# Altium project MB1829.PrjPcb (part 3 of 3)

## Sheet USBHS_TYPEC.SchDoc: USB HS Type-C
size A4; Date: Not used; ApprovedBy: Not used; CheckedBy: Not used; Author: Not used; CompanyName: STMicroelectronics; DrawnBy: Not used; Engineer: Not used; Organization: Not used; Address1: Not used; Address2: Not used; Address3: Not used; Address4: Not used; DocumentNumber: Not used; Revision: Not used; SheetNumber: 9; SheetTotal: 16
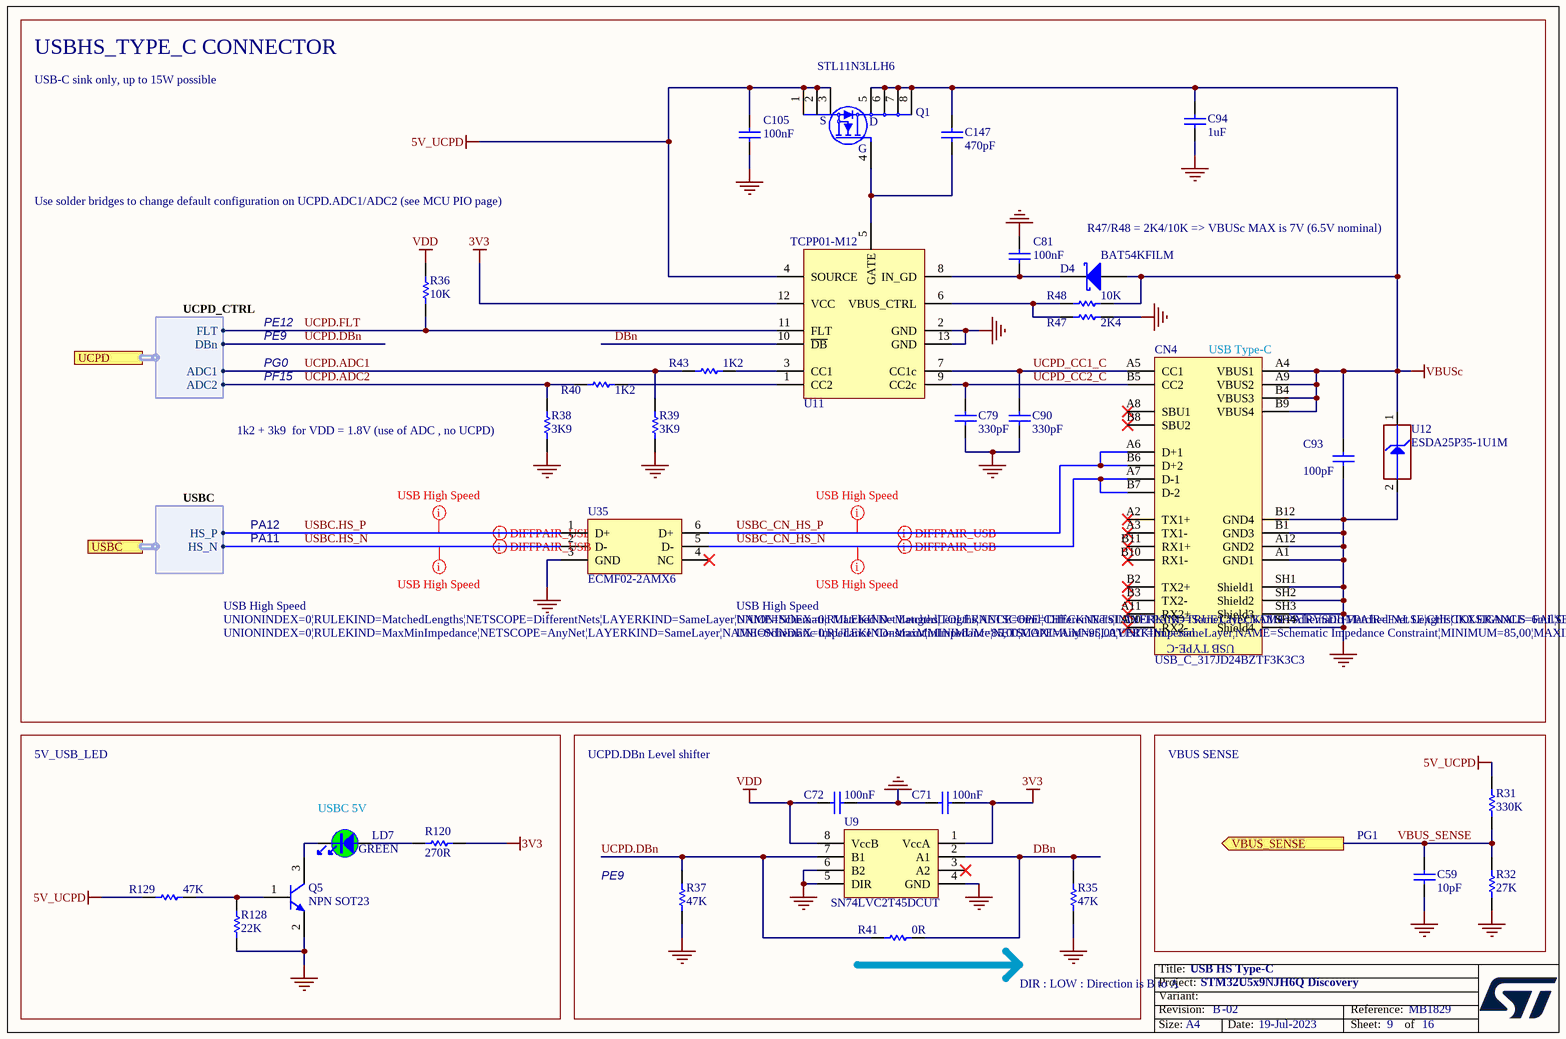
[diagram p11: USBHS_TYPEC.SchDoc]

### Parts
C59  value 10pF  [C0603]  (hidden comment: Capacitor)
C71  value 100nF  [C0402]  (hidden comment: Capacitor)
C72  value 100nF  [C0402]  (hidden comment: Capacitor)
C79  value 330pF  [C0402]  (hidden comment: Capacitor)
C81  value 100nF  [C0603]  (hidden comment: Capacitor)
C90  value 330pF  [C0402]  (hidden comment: Capacitor)
C93  value 100pF  [C0402]  (hidden comment: Capacitor)
C94  value 1uF  [C0402]  (hidden comment: Capacitor)
C105  value 100nF  [C0603]  (hidden comment: Capacitor)
C147  value 470pF  [C0402]  (hidden comment: Capacitor)
CN4  value USB_C_317JD24BZTF3K3C3  [CON_USB-TYPEC_COXOC_317JD24BZTF3K3C3]  (hidden comment: USB_TYPE_C_Receptacle_317JD24BZTF3K3C3)
D4  value BAT54KFILM  [DIO_SOD523_1A_2K]  (hidden comment: SCHOTTKY_1A_2K)
LD7  value GREEN  [LED_0603_OSRAM_LG-Q396-PS-35_GREEN_1A2K_H0P4]  (hidden comment: LED_green)
Q1  STL11N3LLH6  [MOS_POWERFLAT_3P3X3P3_P065]
Q5  value NPN SOT23  [NPN_SOT23]  (hidden comment: 9013-SOT23)
R31  value 330K  [R0603]  (hidden comment: Resistor)
R32  value 27K  [R0603]  (hidden comment: Resistor)
R35  value 47K  [R0603]  (hidden comment: Resistor)
R36  value 10K  [R0603]  (hidden comment: Resistor)
R37  value 47K  [R0603]  (hidden comment: Resistor)
R38  value 3K9  [R0402]  (hidden comment: Resistor)
R39  value 3K9  [R0402]  (hidden comment: Resistor)
R40  value 1K2  [R0402]  (hidden comment: Resistor)
R41  value 0R  [R0402]  (hidden comment: Resistor)
R43  value 1K2  [R0402]  (hidden comment: Resistor)
R47  value 2K4  [R0402]  (hidden comment: Resistor)
R48  value 10K  [R0402]  (hidden comment: Resistor)
R120  value 270R  [R0402]  (hidden comment: Resistor)
R128  value 22K  [R0603]  (hidden comment: Resistor)
R129  value 47K  [R0603]  (hidden comment: Resistor)
U9  SN74LVC2T45DCUT  [ICC_VSSOP8_DCU_R-PDSO-G8_2X2P30_P050]
U11  TCPP01-M12  [ICC_QFN12L-EPAD_3X3_P050]
U12  value ESDA25P35-1U1M  [ESD_QFN1610_2N_1K_2A]  (hidden comment: ESD-TRANSIL)
U35  ECMF02-2AMX6  [ESD_QFN-6L_1P7X1P5_P050]

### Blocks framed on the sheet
USBHS_TYPE_C CONNECTOR: C79 C81 C90 C93 C94 C105 C147 CN4 D4 Q1 R36 R38-R40 R43 R47 R48 U11 U12 U35

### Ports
UCPD (harness UCPD_CTRL), USBC (harness USBC), VBUS_SENSE (out)

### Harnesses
USBC: HS_P, HS_N
UCPD_CTRL: FLT, DBn, ADC1, ADC2

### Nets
3V3: C71.2 R120.2 U9.1(VccA) U11.12(VCC)
5V_UCPD: C105.1 Q1.1(S) Q1.2(S) Q1.3(S) R31.2 R129.1 U11.4(SOURCE)
GND: C59.1 C71.1 C72.2 C79.1 C81.1 C90.1 C93.1 C94.1 C105.2 CN4.A1(GND1) CN4.A12(GND2) CN4.B1(GND3) CN4.B12(GND4) CN4.SH1(Shield1) CN4.SH2(Shield2) CN4.SH3(Shield3) CN4.SH4(Shield4) Q5.2(E) R32.1 R35.1 R37.2 R38.1 R39.1 R47.2 R128.1 U9.4(GND) U9.5(DIR) U9.6(B2) U11.2(GND) U11.13(GND) U12.2(GND) U35.3(GND)
VBUSc: C93.2 C94.2 C147.2 CN4.A4(VBUS1) CN4.A9(VBUS2) CN4.B4(VBUS3) CN4.B9(VBUS4) D4.1(A) Q1.5(D) Q1.6(D) Q1.7(D) Q1.8(D) R48.2 U12.1(IO1)
VDD: C72.1 R36.2 U9.8(VccB)
DBn: R35.2 R41.2 U9.2(A1) U11.10(~{DB})
UCPD.ADC1: R39.2 R43.1 ; port UCPD.ADC1
UCPD.ADC2: R38.2 R40.1 ; port UCPD.ADC2
UCPD.DBn: R37.1 R41.1 U9.7(B1) ; port UCPD.DBn
UCPD.FLT: R36.1 U11.11(FLT) ; port UCPD.FLT
UCPD_CC1_C: C90.2 CN4.A5(CC1) U11.7(CC1c)
UCPD_CC2_C: C79.2 CN4.B5(CC2) U11.9(CC2c)
USBC.HS_N: U35.2(D-) ; port USBC.HS_N
USBC.HS_P: U35.1(D+) ; port USBC.HS_P
USBC_CN_HS_N: CN4.A7(D-1) CN4.B7(D-2) U35.5(D-)
USBC_CN_HS_P: CN4.A6(D+1) CN4.B6(D+2) U35.6(D+)
VBUS_SENSE: C59.2 R31.1 R32.2 ; port VBUS_SENSE
NetC81_2: C81.2 D4.2(K) U11.8(IN_GD)
NetC147_1: C147.1 Q1.4(G) U11.5(GATE)
NetLD7_1: LD7.1 R120.1
NetLD7_2: LD7.2 Q5.3(C)
NetQ5_1: Q5.1(B) R128.2 R129.2
NetR40_2: R40.2 U11.1(CC2)
NetR43_2: R43.2 U11.3(CC1)
NetR47_1: R47.1 R48.1 U11.6(VBUS_CTRL)

Not connected (* = marked no-connect by the designer): CN4 A2(TX1+)* A3(TX1-)* A8(SBU1)* A10(RX2-)* A11(RX2+)* B2(TX2+)* B3(TX2-)* B8(SBU2)* B10(RX1-)* B11(RX1+)*; U9 3(A2)*; U35 4(NC)*

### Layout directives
differential pair; rule Impedance Constraint [Min = 85.00    Max = 95.00    ]: USBC.HS_N, USBC.HS_P, USBC_CN_HS_N, USBC_CN_HS_P
rule Matched Net Lengths [Tolerance = 6mil]; rule Routing Layers [TopLayer - Enabled BottomLayer - Disabled]; rule Impedance Constraint [Min = 85.00    Max = 95.00    ]; net class USB High Speed: USBC.HS_P, USBC_CN_HS_P
rule Matched Net Lengths [Tolerance = 0mil]; rule Routing Layers [TopLayer - Enabled BottomLayer - Disabled]; rule Impedance Constraint [Min = 85.00    Max = 95.00    ]; net class USB High Speed: USBC.HS_N, USBC_CN_HS_N

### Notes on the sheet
- USB-C sink only, up to 15W possible
- Use solder bridges to change default configuration on UCPD.ADC1/ADC2 (see MCU PIO page)
- (near D4) R47/R48 = 2K4/10K => VBUSc MAX is 7V (6.5V nominal)
- PG0
- PF15
- PE12
- PE9
- (near CN4) USB Type-C
- (near R38) 1k2 + 3k9  for VDD = 1.8V (use of ADC , no UCPD)
- PA12
- PA11
- 5V_USB_LED
- UCPD.DBn Level shifter
- VBUS SENSE
- (near LD7) USBC 5V
- PG1
- (near R41) DIR : LOW : Direction is B to A

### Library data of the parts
C59 = MCD-00637: Capacitor, MLCC, 10pF, 50V, NPO, +/-5%, 0603, T=0.8mm; Manufacturer_Part_Number: CC0603JRNPO9BN100; Manufacturer: YAGEO; Part_Preference: Recommended; Order_Code_RS: 616-9054; Component_Country_Of_Origin: China
C71 C72 = MCD-00006: Capacitor, MLCC, 100nF, 16V, X7R, +/-10%, 0402, T=0.5mm; Manufacturer_Part_Number: CC0402KRX7R7BB104; Manufacturer: YAGEO; Part_Preference: Recommended; Order_Code_RS: 616-9701; Component_Country_Of_Origin: China
C79 C90 = MCD-01579: Capacitor, MLCC, 330pF, 50V, NPO, +/-5%, 0402, T=0.5mm; Manufacturer: YAGEO; Manufacturer_Part_Number: CC0402JRNPO9BN331; Part_Preference: Recommended; Component_Country_Of_Origin: China
C81 C105 = MCD-01099: Capacitor, MLCC, 100nF, 50V, X7R, +/-10%, 0603, T=0.8mm; Manufacturer_Part_Number: CC0603KRX7R9BB104; Manufacturer: YAGEO; BMS_Part_Number: 9142278; Part_Preference: Recommended; Order_Code_RS: 669-8767; Component_Country_Of_Origin: China
C93 = MCD-00205: Capacitor, MLCC, 100pF, 50V, NPO, +/-5%, 0402, T=0.5mm; Part_Preference: Recommended; Manufacturer: YAGEO; Manufacturer_Part_Number: CC0402JRNPO9BN101; Component_Country_Of_Origin: China
C94 = MCD-02609: Capacitor, MLCC, 1uF, 25V, X5R, +/-10%, 0402, T=0.5mm; Part_Preference: Recommended; Manufacturer: YAGEO; Manufacturer_Part_Number: CC0402KRX5R8BB105
C147 = MCD-00724: Capacitor, MLCC, 470pF, 50V, NPO, +/-5%, 0402, T=0.5mm; Part_Preference: Recommended; Manufacturer: YAGEO; Manufacturer_Part_Number: CC0402JRNPO9BN471; Order_Code_RS: 199-2186; Component_Country_Of_Origin: China
CN4 = MCD-01108: USB_TypeC, SMD+DIP, T= 2.96mm (for 1.6mm pcb); Part_Type: Connector; Manufacturer: CHANT SINCERE (COXOC); Part_Preference: Recommended; Component_Country_Of_Origin: Unknown
D4 = MCD-01677: Small signal Schottky diodes; Part_Type: Diode; Manufacturer: STMICROELECTRONICS; BMS_Part_Number: 9151123; Part_Preference: Recommended; Manufacturer_HQ_COO: EU; Component_Country_Of_Origin: China
LD7 = MCD-00588: LED Green, 0603 SMD, Forward Voltage Typ=2V, Max=2.5V; Part_Type: Display; Manufacturer_Part_Number: LG Q396-PS-35; Manufacturer: OSRAM OPTO SEMICONDUCTORS; Part_Preference: Recommended; Alternate_Internal_Part_Number: MCD-02400; Component_Country_Of_Origin: Unknown; ShowFields: YES; ID: 3155
Q1 = MCD-01810: N-channel 30 V, 6 mΩ typ, 11 A STripFET™ H6, Power MOSFET in a PowerFLAT™ 3.3x3.3 package; BMS_Part_Number: 9153561; Part_Type: IC; Part_Preference: Recommended; Manufacturer: STMICROELECTRONICS; Manufacturer_HQ_COO: EU; Component_Country_Of_Origin: China
Q5 = MCD-00073: NPN Bipolar Transistor; Part_Type: IC; Manufacturer_Part_Number: BSR14; Manufacturer: ON SEMICONDUCTOR; Part_Preference: Recommended; Component_Country_Of_Origin: Unknown
R31 = MCD-00458: Resistor, 330K, 0603, +/-1%, 1/10W; Manufacturer_Part_Number: RC0603FR-07330KL; Manufacturer: YAGEO; Part_Preference: Recommended; Component_Country_Of_Origin: China
R32 = MCD-00444: Resistor, 27K, 0603, +/-1%, 1/10W; Manufacturer_Part_Number: RC0603FR-0727KL; Manufacturer: YAGEO; Part_Preference: Recommended; Component_Country_Of_Origin: China
R35 = MCD-00222: Resistor, 47K, 0603, 1%, 1/10W; Part_Preference: Recommended; Manufacturer: YAGEO; Manufacturer_Part_Number: RC0603FR-0747KL; Component_Country_Of_Origin: China
R36 = MCD-00220: Resistor, 10K, 0603, +/-1%, 1/10W; Manufacturer_Part_Number: RC0603FR-0710KL; Manufacturer: YAGEO; Part_Preference: Recommended; Component_Country_Of_Origin: China
R37 R129 = MCD-00222: Resistor, 47K, 0603, 1%, 1/10W; Manufacturer_Part_Number: RC0603FR-0747KL; Manufacturer: YAGEO; Part_Preference: Recommended; Component_Country_Of_Origin: China
R38 R39 = MCD-02455: Resistor, 3K9, 0402, +/-1%, 1/16W, +/-100ppm/°C; Part_Preference: Recommended; Manufacturer: YAGEO; Manufacturer_Part_Number: RC0402FR-073K9L; Order_Code_RS: 198-7783; Component_Country_Of_Origin: China
R40 R43 = MCD-00373: Resistor, 1K2, 0402, +/-1%, 1/16W; Part_Preference: Recommended; Manufacturer: YAGEO; Manufacturer_Part_Number: RC0402FR-071K2L; Component_Country_Of_Origin: China
R41 = MCD-00052: Resistor, 0R, 0402, +/-5%, 1/16W; Manufacturer_Part_Number: RC0402JR-070RL; Manufacturer: YAGEO; Part_Preference: Recommended; Order_Code_RS: 618-5804; Component_Country_Of_Origin: China
R47 = MCD-00433: Resistor, 2K4, 0402, +/-1%, 1/16W; Part_Preference: Recommended; Manufacturer: YAGEO; Manufacturer_Part_Number: RC0402FR-072K4L; Component_Country_Of_Origin: China
R48 = MCD-00053: Resistor, 10K, 0402, +/-1%, 1/16W; BMS_Part_Number: 9131590; Part_Preference: Recommended; Manufacturer: YAGEO; Manufacturer_Part_Number: RC0402FR-0710KL; Component_Country_Of_Origin: China
R120 = MCD-00441: Resistor, 270R, 0402, +/-1%, 1/16W; Manufacturer: YAGEO; Manufacturer_Part_Number: RC0402FR-07270RL; Part_Preference: Recommended; Component_Country_Of_Origin: China; ShowFields: YES; ID: 2838
R128 = MCD-00430: Resistor, 22K, 0603, +/-1%, 1/10W; Manufacturer_Part_Number: RC0603FR-0722KL; Manufacturer: YAGEO; Part_Preference: Recommended; Component_Country_Of_Origin: China
U9 = MCD-00264: Dual bit dual supply bus transceiver; Part_Type: IC; Manufacturer: TEXAS INSTRUMENTS; BMS_Part_Number: 9169311; Part_Preference: Recommended; Component_Country_Of_Origin: Thailand
U11 = MCD-01809: USB Type-C Port Protection for USB Power Delivery, PPS compliant; Part_Type: IC; Manufacturer: STMICROELECTRONICS; BMS_Part_Number: 9151145; Part_Preference: Recommended; Manufacturer_HQ_COO: EU; Component_Country_Of_Origin: Malaysia
U12 = MCD-01207: High power Transient voltage suppressor:25V/35A EOS and ESD transients protection.; Part_Type: Diode; Manufacturer: STMICROELECTRONICS; BMS_Part_Number: 9179045; Part_Preference: Recommended; Manufacturer_HQ_COO: EU; Component_Country_Of_Origin: China
U35 = MCD-00649: Common mode filter with ESD protection for USB 2.0 interface; Part_Type: Diode; Manufacturer: STMICROELECTRONICS; BMS_Part_Number: 9151138; Part_Preference: Recommended; Manufacturer_HQ_COO: EU; Component_Country_Of_Origin: China

## Sheet eMMC.SchDoc: eMMC
size A4; Date: Not used; ApprovedBy: Not used; CheckedBy: Not used; Author: Not used; CompanyName: STMicroelectronics; DrawnBy: Not used; Engineer: Not used; Organization: Not used; Address1: Not used; Address2: Not used; Address3: Not used; Address4: Not used; DocumentNumber: Not used; Revision: Not used; SheetNumber: 8; SheetTotal: 16
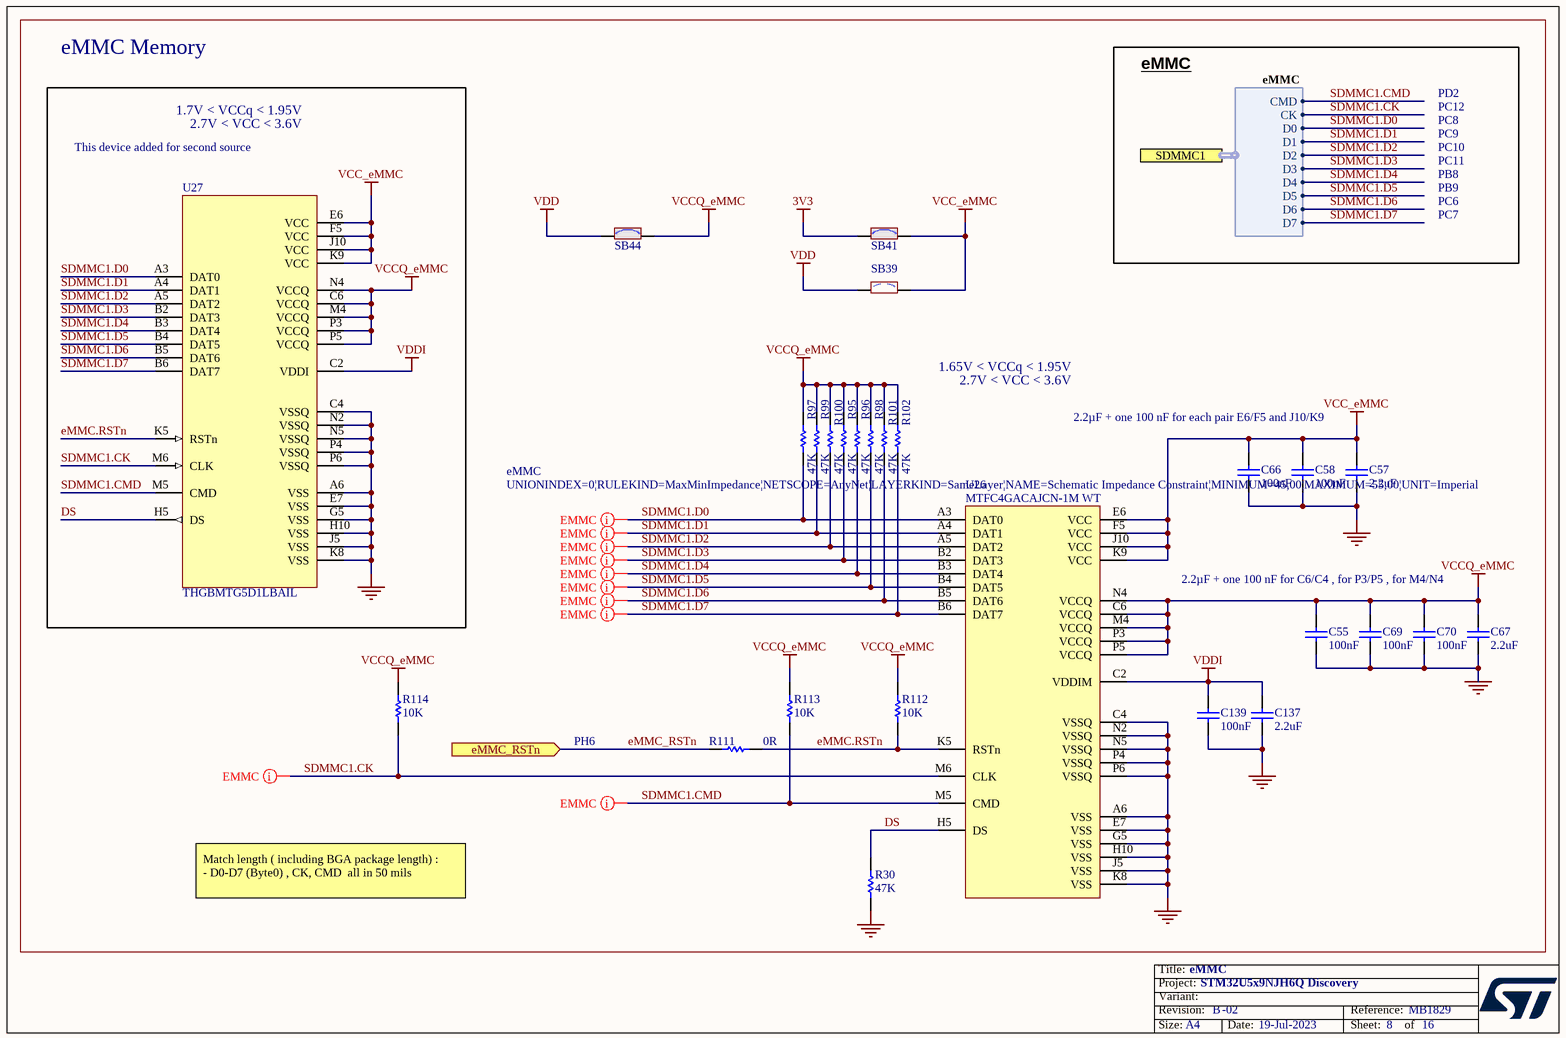
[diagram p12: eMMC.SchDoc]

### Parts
C55  value 100nF  [C0402]  (hidden comment: Capacitor)
C57  value 2.2uF  [C0603]  (hidden comment: Capacitor)
C58  value 100nF  [C0402]  (hidden comment: Capacitor)
C66  value 100nF  [C0402]  (hidden comment: Capacitor)
C67  value 2.2uF  [C0603]  (hidden comment: Capacitor)
C69  value 100nF  [C0402]  (hidden comment: Capacitor)
C70  value 100nF  [C0402]  (hidden comment: Capacitor)
C137  value 2.2uF  [C0603]  (hidden comment: Capacitor)
C139  value 100nF  [C0402]  (hidden comment: Capacitor)
R30  value 47K  [R0402]  (hidden comment: Resistor)
R95  value 47K  [R0402]  (hidden comment: Resistor)
R96  value 47K  [R0402]  (hidden comment: Resistor)
R97  value 47K  [R0402]  (hidden comment: Resistor)
R98  value 47K  [R0402]  (hidden comment: Resistor)
R99  value 47K  [R0402]  (hidden comment: Resistor)
R100  value 47K  [R0402]  (hidden comment: Resistor)
R101  value 47K  [R0402]  (hidden comment: Resistor)
R102  value 47K  [R0402]  (hidden comment: Resistor)
R111  value 0R  [R0402]  (hidden comment: Resistor)
R112  value 10K  [R0402]  (hidden comment: Resistor)
R113  value 10K  [R0402]  (hidden comment: Resistor)
R114  value 10K  [R0402]  (hidden comment: Resistor)
SB39  SB_OFF  [SOLDER-BRIDGE_R0402-0R]  (value not drawn)
SB41  SB_ON  [SOLDER-BRIDGE_R0402-0R]  (value not drawn)
SB44  SB_ON  [SOLDER-BRIDGE_R0402-0R]  (value not drawn)
U26  MTFC4GACAJCN-1M WT  [ICC_P-WFBGA153_13X11P5_P050]
U27  value THGBMTG5D1LBAIL  [ICC_P-WFBGA153_13X11P5_P050]  (hidden comment: eMMC_THGBMTG5D1LBAIL)

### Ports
eMMC_RSTn (in), SDMMC1 (harness eMMC)

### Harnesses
eMMC: D0, CMD, CK, D1, D2, D3, D4, D5, D6, D7

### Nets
3V3: SB41.1
GND: C55.1 C57.1 C58.1 C66.1 C67.1 C69.1 C70.1 C137.1 C139.1 R30.1 U26.A6(VSS) U26.C4(VSSQ) U26.E7(VSS) U26.G5(VSS) U26.H10(VSS) U26.J5(VSS) U26.K8(VSS) U26.N2(VSSQ) U26.N5(VSSQ) U26.P4(VSSQ) U26.P6(VSSQ) U27.A6(VSS) U27.C4(VSSQ) U27.E7(VSS) U27.G5(VSS) U27.H10(VSS) U27.J5(VSS) U27.K8(VSS) U27.N2(VSSQ) U27.N5(VSSQ) U27.P4(VSSQ) U27.P6(VSSQ)
VCC_eMMC: C57.2 C58.2 C66.2 SB39.2 SB41.2 U26.E6(VCC) U26.F5(VCC) U26.J10(VCC) U26.K9(VCC) U27.E6(VCC) U27.F5(VCC) U27.J10(VCC) U27.K9(VCC)
VCCQ_eMMC: C55.2 C67.2 C69.2 C70.2 R95.2 R96.2 R97.2 R98.2 R99.2 R100.2 R101.2 R102.2 R112.2 R113.2 R114.2 SB44.2 U26.C6(VCCQ) U26.M4(VCCQ) U26.N4(VCCQ) U26.P3(VCCQ) U26.P5(VCCQ) U27.C6(VCCQ) U27.M4(VCCQ) U27.N4(VCCQ) U27.P3(VCCQ) U27.P5(VCCQ)
VDD: SB39.1 SB44.1
VDDI: C137.2 C139.2 U26.C2(VDDIM) U27.C2(VDDI)
DS: R30.2 U26.H5(DS) U27.H5(DS)
eMMC.RSTn: R111.2 R112.1 U26.K5(RSTn) U27.K5(RSTn)
eMMC_RSTn: R111.1 ; port eMMC_RSTn
SDMMC1.CK: R114.1 U26.M6(CLK) U27.M6(CLK) ; port SDMMC1.CK
SDMMC1.CMD: R113.1 U26.M5(CMD) U27.M5(CMD) ; port SDMMC1.CMD
SDMMC1.D0: R97.1 U26.A3(DAT0) U27.A3(DAT0) ; port SDMMC1.D0
SDMMC1.D1: R99.1 U26.A4(DAT1) U27.A4(DAT1) ; port SDMMC1.D1
SDMMC1.D2: R100.1 U26.A5(DAT2) U27.A5(DAT2) ; port SDMMC1.D2
SDMMC1.D3: R95.1 U26.B2(DAT3) U27.B2(DAT3) ; port SDMMC1.D3
SDMMC1.D4: R96.1 U26.B3(DAT4) U27.B3(DAT4) ; port SDMMC1.D4
SDMMC1.D5: R98.1 U26.B4(DAT5) U27.B4(DAT5) ; port SDMMC1.D5
SDMMC1.D6: R101.1 U26.B5(DAT6) U27.B5(DAT6) ; port SDMMC1.D6
SDMMC1.D7: R102.1 U26.B6(DAT7) U27.B6(DAT7) ; port SDMMC1.D7

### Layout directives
rule Matched Net Lengths [Tolerance = 20mil]; rule Impedance Constraint [Min = 45.00    Max = 55.00    ]; net class eMMC: SDMMC1.D0
rule Matched Net Lengths [Tolerance = 20mil]; rule Impedance Constraint [Min = 45.00    Max = 55.00    ]: SDMMC1.CK, SDMMC1.D1, SDMMC1.D2, SDMMC1.D3, SDMMC1.D4, SDMMC1.D5, SDMMC1.D6, SDMMC1.D7
rule Matched Net Lengths [Tolerance = 50mil]; rule Impedance Constraint [Min = 45.00    Max = 55.00    ]: SDMMC1.CMD

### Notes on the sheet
- eMMC Memory
- 1.7V < VCCq < 1.95V
- 2.7V < VCC < 3.6V
- eMMC
- PC12
- PD2
- This device added for second source
- PC8
- PC9
- PC10
- PC11
- PB8
- PC6
- PC7
- PB9
- 1.65V < VCCq < 1.95V
- 2.2µF + one 100 nF for each pair E6/F5 and J10/K9
- 2.2µF + one 100 nF for C6/C4 , for P3/P5 , for M4/N4
- PH6
- Match length ( including BGA package length) :
  - D0-D7 (Byte0) , CK, CMD  all in 50 mils

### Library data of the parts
C55 C58 C66 C69 C70 C139 = MCD-00006: as C71 on sheet USBHS_TYPEC
C57 C67 C137 = MCD-00012: Capacitor, MLCC, 2.2uF, 10V, X5R, +/- 10%, 0603, T=0.8mm; Manufacturer_Part_Number: CC0603KRX5R6BB225; Manufacturer: YAGEO; BMS_Part_Number: 9142010; Part_Preference: Recommended; Component_Country_Of_Origin: China
R30 R95-R102 = MCD-00063: Resistor, 47K, 0402, +/-1%, 1/16W; Manufacturer_Part_Number: RC0402FR-0747KL; Manufacturer: YAGEO; Part_Preference: Recommended; Component_Country_Of_Origin: China
R111 = MCD-00052: as R41 on sheet USBHS_TYPEC
R112-R114 = MCD-00053: Resistor, 10K, 0402, +/-1%, 1/16W; Manufacturer_Part_Number: RC0402FR-0710KL; Manufacturer: YAGEO; BMS_Part_Number: 9131590; Part_Preference: Recommended; Component_Country_Of_Origin: China
SB39 = MCD-02162: Solder Bridge 0402 OFF; Part_Type: Misc; Manufacturer_Part_Number: RC0402JR-070RL; Manufacturer: YAGEO; Part_Preference: Recommended; Order_Code_RS: 618-5804; Component_Country_Of_Origin: China
SB41 SB44 = MCD-01618: Solder Bridge 0402 ON; Part_Type: Misc; Manufacturer_Part_Number: RC0402JR-070RL; Manufacturer: YAGEO; Part_Preference: Recommended; Order_Code_RS: 618-5804; Component_Country_Of_Origin: China
U26 = MCD-01137: 4G MultiMediaCard (MMC) controller and NAND Flash; Part_Type: IC; Manufacturer: MICRON; BMS_Part_Number: 9171977; Part_Preference: Recommended; Component_Country_Of_Origin: Singapore
U27 = MCD-02799: Memory, eMMC, 4GB, 15nm ,WFBGA , 153 pins; Part_Type: IC; Part_Preference: Recommended; Manufacturer: KIOXIA; Component_Country_Of_Origin: Unknown; ShowFields: YES; ID: 4911

## Sheet HEXADECASPI_PSRAM.SchDoc: HEXADECASPI PSRAM
size A4; Date: Not used; ApprovedBy: Not used; CheckedBy: Not used; Author: Not used; CompanyName: STMicroelectronics; DrawnBy: Not used; Engineer: Not used; Organization: Not used; Address1: Not used; Address2: Not used; Address3: Not used; Address4: Not used; DocumentNumber: Not used; Revision: Not used; SheetNumber: 7; SheetTotal: 16
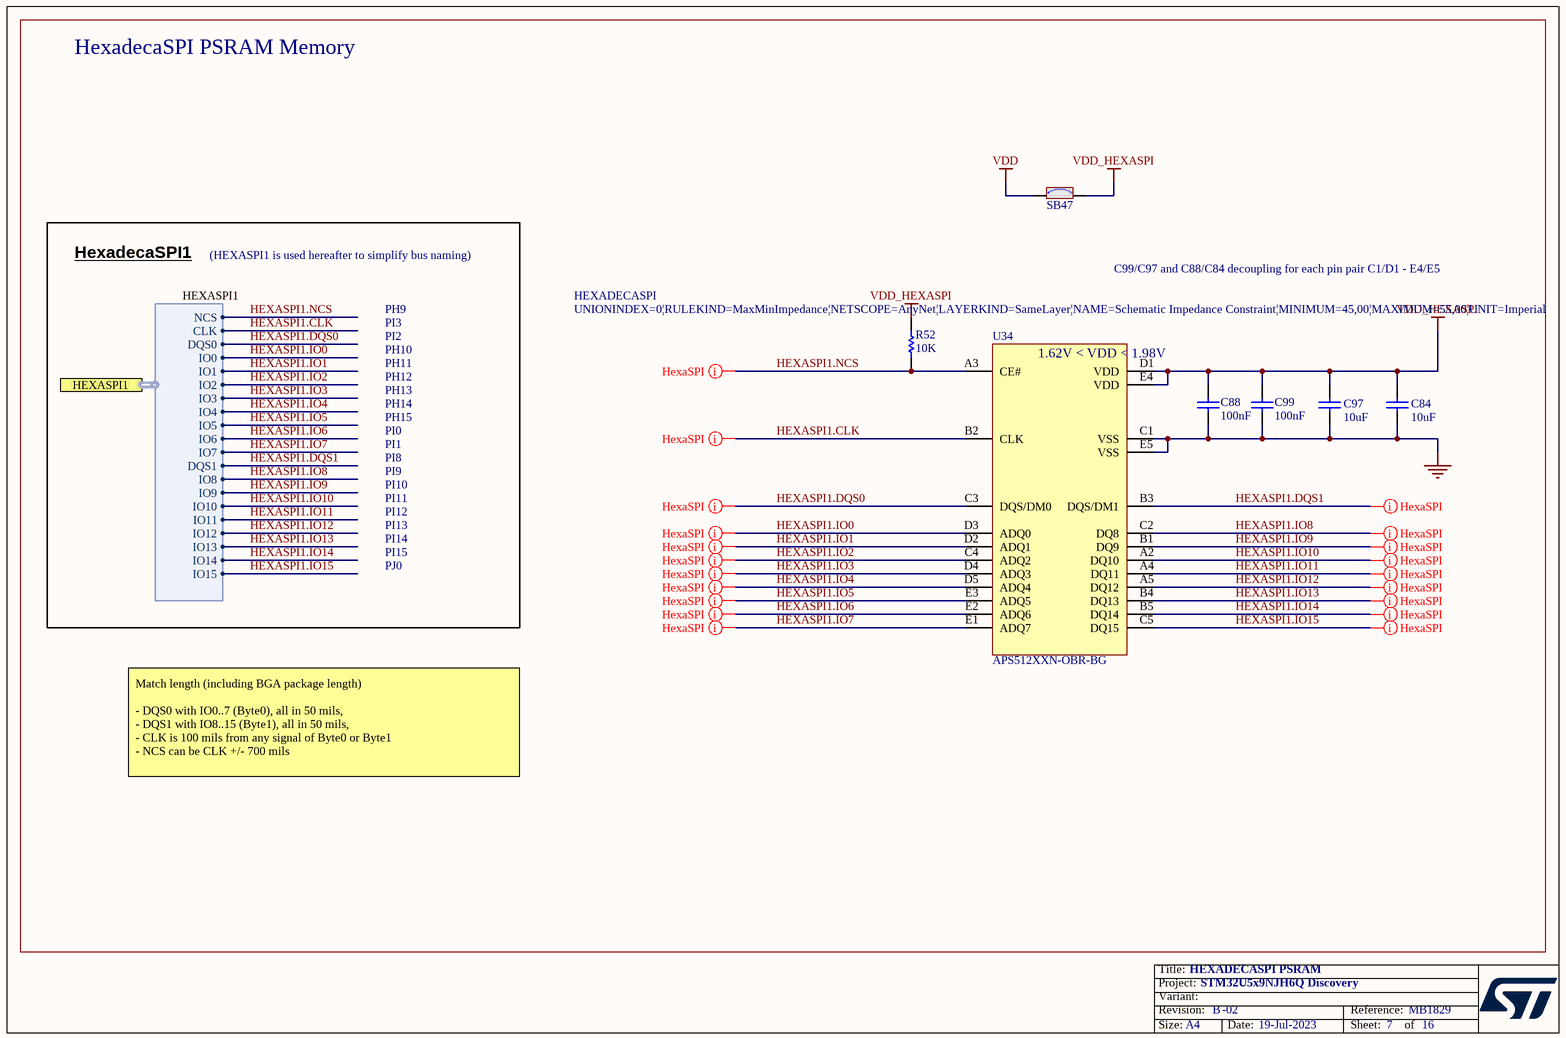
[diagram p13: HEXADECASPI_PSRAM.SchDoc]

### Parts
C84  value 10uF  [C0603_H0P8]  (hidden comment: Capacitor)
C88  value 100nF  [C0402]  (hidden comment: Capacitor)
C97  value 10uF  [C0603_H0P8]  (hidden comment: Capacitor)
C99  value 100nF  [C0402]  (hidden comment: Capacitor)
R52  value 10K  [R0402]  (hidden comment: Resistor)
SB47  SB_ON  [SOLDER-BRIDGE_R0402-0R]  (value not drawn)
U34  value APS512XXN-OBR-BG  [ICC_BGA24_5X5-BALL-ARRAY_6X8_P1]  (hidden comment: APS256XXN-OBR-BG)

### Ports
HEXASPI1 (harness HEXASPI1)

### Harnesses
HEXASPI1: IO1, IO0, DQS0, NCS, IO2, IO3, IO5, IO4, IO6, IO7, CLK, DQS1, IO8, IO9, IO10, IO11, IO12, IO13, IO14, IO15

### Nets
GND: C84.1 C88.1 C97.1 C99.1 U34.C1(VSS) U34.E5(VSS)
VDD: SB47.1
VDD_HEXASPI: C84.2 C88.2 C97.2 C99.2 R52.2 SB47.2 U34.D1(VDD) U34.E4(VDD)
HEXASPI1.CLK: U34.B2(CLK) ; port HEXASPI1.CLK
HEXASPI1.DQS0: U34.C3(DQS/DM0) ; port HEXASPI1.DQS0
HEXASPI1.DQS1: U34.B3(DQS/DM1) ; port HEXASPI1.DQS1
HEXASPI1.IO0: U34.D3(ADQ0) ; port HEXASPI1.IO0
HEXASPI1.IO1: U34.D2(ADQ1) ; port HEXASPI1.IO1
HEXASPI1.IO2: U34.C4(ADQ2) ; port HEXASPI1.IO2
HEXASPI1.IO3: U34.D4(ADQ3) ; port HEXASPI1.IO3
HEXASPI1.IO4: U34.D5(ADQ4) ; port HEXASPI1.IO4
HEXASPI1.IO5: U34.E3(ADQ5) ; port HEXASPI1.IO5
HEXASPI1.IO6: U34.E2(ADQ6) ; port HEXASPI1.IO6
HEXASPI1.IO7: U34.E1(ADQ7) ; port HEXASPI1.IO7
HEXASPI1.IO8: U34.C2(DQ8) ; port HEXASPI1.IO8
HEXASPI1.IO9: U34.B1(DQ9) ; port HEXASPI1.IO9
HEXASPI1.IO10: U34.A2(DQ10) ; port HEXASPI1.IO10
HEXASPI1.IO11: U34.A4(DQ11) ; port HEXASPI1.IO11
HEXASPI1.IO12: U34.A5(DQ12) ; port HEXASPI1.IO12
HEXASPI1.IO13: U34.B4(DQ13) ; port HEXASPI1.IO13
HEXASPI1.IO14: U34.B5(DQ14) ; port HEXASPI1.IO14
HEXASPI1.IO15: U34.C5(DQ15) ; port HEXASPI1.IO15
HEXASPI1.NCS: R52.1 U34.A3(CE#) ; port HEXASPI1.NCS

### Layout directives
rule Matched Net Lengths [Tolerance = 1000mil]; net class HEXASPI; rule Impedance Constraint [Min = 50.00    Max = 60.00    ]; rule Routing Layers [TopLayer - Enabled BottomLayer - Disabled]: HEXASPI1.NCS
rule Matched Net Lengths [Tolerance = 20mil]; net class HEXASPI; rule Impedance Constraint [Min = 45.00    Max = 55.00    ]; rule Routing Layers [TopLayer - Enabled BottomLayer - Disabled]: HEXASPI1.DQS1, HEXASPI1.IO0, HEXASPI1.IO1, HEXASPI1.IO2, HEXASPI1.IO3, HEXASPI1.IO4, HEXASPI1.IO5, HEXASPI1.IO6, HEXASPI1.IO7, HEXASPI1.IO8, HEXASPI1.IO9, HEXASPI1.IO10, HEXASPI1.IO11, HEXASPI1.IO12, HEXASPI1.IO13, HEXASPI1.IO14, HEXASPI1.IO15
rule Matched Net Lengths [Tolerance = 20mil]; net class HEXADECASPI; rule Impedance Constraint [Min = 45.00    Max = 55.00    ]; rule Routing Layers [TopLayer - Enabled BottomLayer - Disabled]: HEXASPI1.CLK
rule Matched Net Lengths [Tolerance = 20mil]; net class HEXASPI; rule Impedance Constraint [Min = 50.00    Max = 60.00    ]; rule Routing Layers [TopLayer - Enabled BottomLayer - Disabled]: HEXASPI1.DQS0

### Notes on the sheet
- HexadecaSPI PSRAM Memory
- HexadecaSPI1
- (HEXASPI1 is used hereafter to simplify bus naming)
- PH9
- C99/C97 and C88/C84 decoupling for each pin pair C1/D1 - E4/E5
- PH10
- PH11
- PH12
- PI2
- PI3
- 1.62V < VDD < 1.98V
- PH13
- PH14
- PH15
- PI0
- PI1
- PI8
- PI9
- PI10
- PI11
- PI12
- PI13
- PI14
- PI15
- PJ0
- Match length (including BGA package length)
  - DQS0 with IO0..7 (Byte0), all in 50 mils,
  - DQS1 with IO8..15 (Byte1), all in 50 mils,
  - CLK is 100 mils from any signal of Byte0 or Byte1
  - NCS can be CLK +/- 700 mils

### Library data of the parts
C84 C97 = MCD-02605: Capacitor, MLCC, 10uF, 10V, X5R, +/-10%, 0603, T=0.8mm; Manufacturer_Part_Number: CC0603KRX5R6BB106; Manufacturer: YAGEO; Part_Preference: Recommended; Order_Code_RS: 2006536; ShowFields: YES; ID: 4711
C88 C99 = MCD-00006: as C71 on sheet USBHS_TYPEC
R52 = MCD-00053: as R112-R114 on sheet eMMC
SB47 = MCD-01618: as SB41 on sheet eMMC
U34 = MCD-02904: Memory,Hexa-SPI-PSRAM,512Mb,x8x16,200MHz,1.8V,DDR,BGA24, PASR LVCMOS; Part_Type: IC; Manufacturer: AP MEMORY TECHNOLOGY CORP.; Part_Preference: Recommended; ShowFields: YES; ID: 5020

## Sheet DSI_LCD.SchDoc: DSI LCD
size A4; Date: Not used; ApprovedBy: Not used; CheckedBy: Not used; Author: Not used; CompanyName: STMicroelectronics; DrawnBy: Not used; Engineer: Not used; Organization: Not used; Address1: Not used; Address2: Not used; Address3: Not used; Address4: Not used; DocumentNumber: Not used; Revision: Not used; SheetNumber: 10; SheetTotal: 16
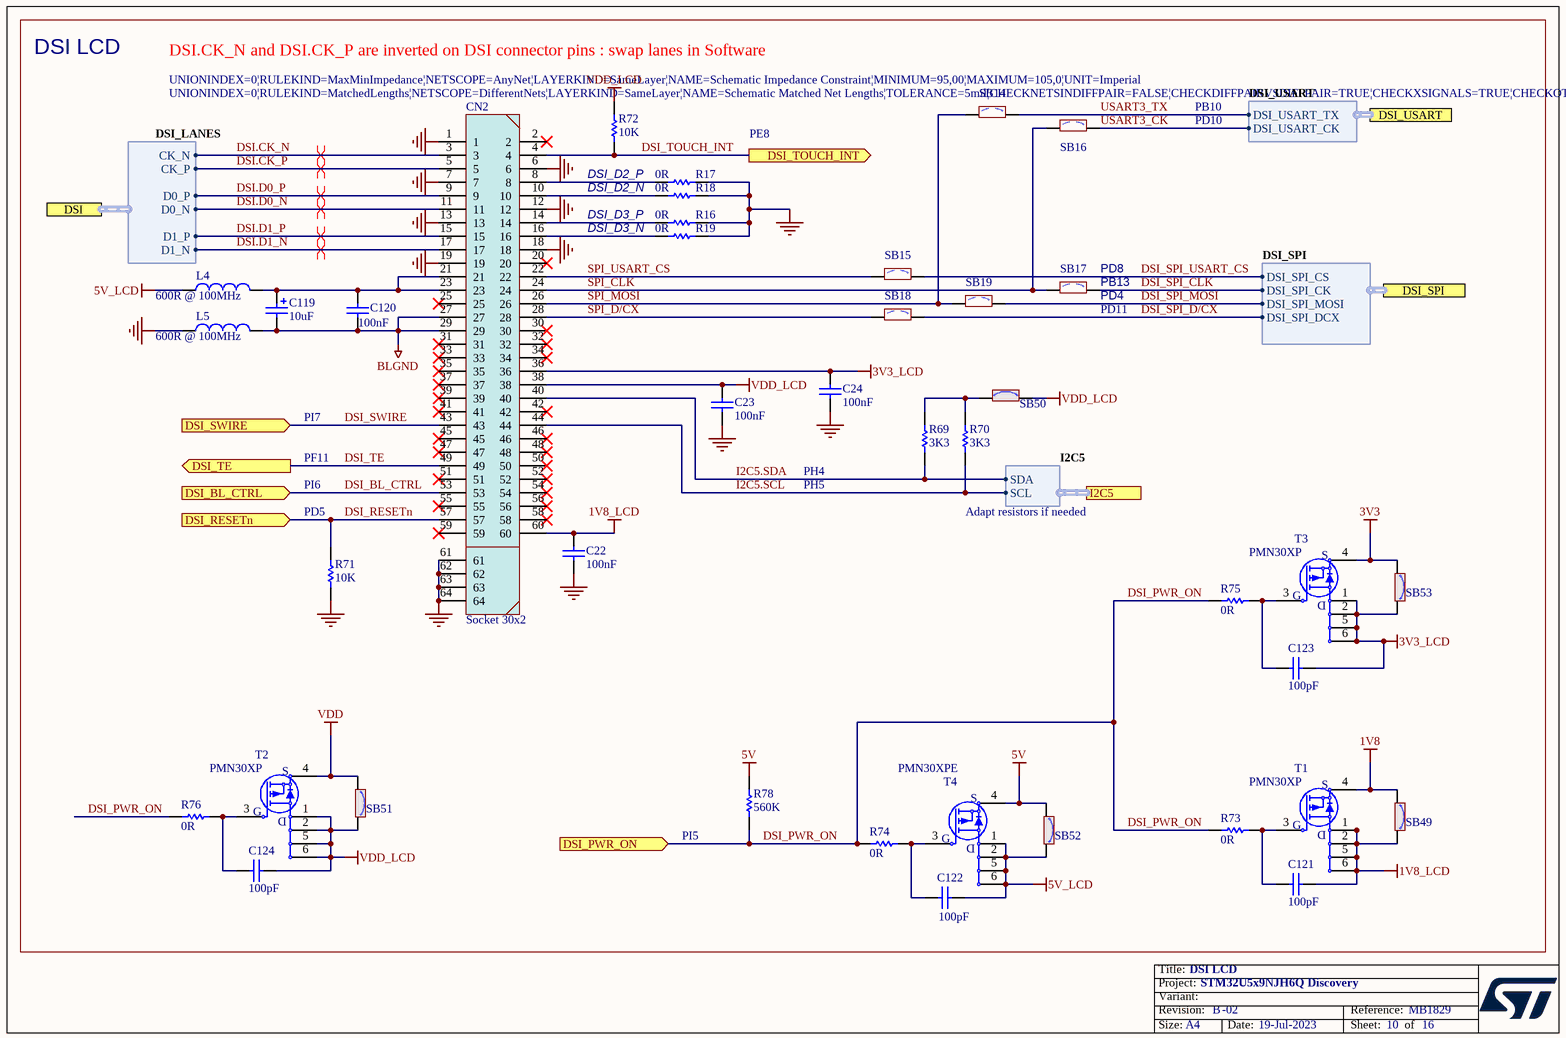
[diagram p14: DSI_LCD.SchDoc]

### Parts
C22  value 100nF  [C0402]  (hidden comment: Capacitor)
C23  value 100nF  [C0402]  (hidden comment: Capacitor)
C24  value 100nF  [C0402]  (hidden comment: Capacitor)
C119  value 10uF  [CPOL_TAJ-A_1206_H180]  (hidden comment: Cap_POL_TANA)
C120  value 100nF  [C0402]  (hidden comment: Capacitor)
C121  value 100pF  [C0603]  (hidden comment: Capacitor)
C122  value 100pF  [C0603]  (hidden comment: Capacitor)
C123  value 100pF  [C0603]  (hidden comment: Capacitor)
C124  value 100pF  [C0603]  (hidden comment: Capacitor)
CN2  value Socket 30x2  [CON_SAMTEC_QSH-030-01-F-D-A_no-LCD-MB1835]  (hidden comment: Socket QSH-030-01-F-D-A_DSI_LCD)
L4  value 600R @ 100MHz  [L0603]  (hidden comment: BEAD)
L5  value 600R @ 100MHz  [L0603]  (hidden comment: BEAD)
R16  value 0R  [R0402]  (hidden comment: Resistor)
R17  value 0R  [R0402]  (hidden comment: Resistor)
R18  value 0R  [R0402]  (hidden comment: Resistor)
R19  value 0R  [R0402]  (hidden comment: Resistor)
R69  value 3K3  [R0402]  (hidden comment: Resistor)
R70  value 3K3  [R0402]  (hidden comment: Resistor)
R71  value 10K  [R0402]  (hidden comment: Resistor)
R72  value 10K  [R0402]  (hidden comment: Resistor)
R73  value 0R  [R0603]  (hidden comment: Resistor)
R74  value 0R  [R0603]  (hidden comment: Resistor)
R75  value 0R  [R0603]  (hidden comment: Resistor)
R76  value 0R  [R0603]  (hidden comment: Resistor)
R78  value 560K  [R0402]  (hidden comment: Resistor)
SB14  SB_OFF  [SOLDER-BRIDGE_R0402-0R]  (value not drawn)
SB15  SB_OFF  [SOLDER-BRIDGE_R0402-0R]  (value not drawn)
SB16  SB_OFF  [SOLDER-BRIDGE_R0402-0R]  (value not drawn)
SB17  SB_OFF  [SOLDER-BRIDGE_R0402-0R]  (value not drawn)
SB18  SB_OFF  [SOLDER-BRIDGE_R0402-0R]  (value not drawn)
SB19  SB_OFF  [SOLDER-BRIDGE_R0402-0R]  (value not drawn)
SB49  SB_ON  [SOLDER-BRIDGE_R0402-0R]  (value not drawn)
SB50  SB_ON  [SOLDER-BRIDGE_R0402-0R]  (value not drawn)
SB51  SB_ON  [SOLDER-BRIDGE_R0402-0R]  (value not drawn)
SB52  SB_ON  [SOLDER-BRIDGE_R0402-0R]  (value not drawn)
SB53  SB_ON  [SOLDER-BRIDGE_R0402-0R]  (value not drawn)
T1  PMN30XP  [MOS_SOT23-6L]
T2  PMN30XP  [MOS_SOT23-6L]
T3  PMN30XP  [MOS_SOT23-6L]
T4  value PMN30XPE  [MOS_TSOP6_CASE-457_P095]  (hidden comment: PMN30XP)

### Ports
DSI (harness DSI_LANES), DSI_BL_CTRL (in), DSI_PWR_ON (in), DSI_RESETn (in), DSI_SPI (harness DSI_SPI), DSI_SWIRE (in), DSI_TE (out), DSI_TOUCH_INT (out), DSI_USART (harness DSI_USART), I2C5 (harness I2C5)

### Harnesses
I2C5: SDA, SCL
DSI_USART: DSI_USART_CK, DSI_USART_TX
DSI_SPI: DSI_SPI_CS, DSI_SPI_MOSI, DSI_SPI_CK, DSI_SPI_DCX
DSI_LANES: CK_P, CK_N, D0_P, D0_N, D1_N, D1_P

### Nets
1V8: SB49.1 T1.4(S)
1V8_LCD: C22.2 C121.2 CN2.60 SB49.2 T1.1(S) T1.2(S) T1.5(D) T1.6(D)
3V3: SB53.1 T3.4(S)
3V3_LCD: C24.2 C123.2 CN2.36 SB53.2 T3.1(S) T3.2(S) T3.5(D) T3.6(D)
5V: R78.2 SB52.1 T4.4(S)
5V_LCD: C122.2 L4.1 SB52.2 T4.1(S) T4.2(S) T4.5(D) T4.6(D)
BLGND: C119.2 C120.1 CN2.27 CN2.29 L5.2
GND: C22.1 C23.1 C24.1 CN2.1 CN2.6 CN2.7 CN2.12 CN2.13 CN2.18 CN2.19 CN2.61 CN2.62 CN2.63 CN2.64 L5.1 R16.2 R17.2 R18.2 R19.2 R71.1
VDD: SB51.1 T2.4(S)
VDD_LCD: C23.2 C124.2 CN2.38 R72.2 SB50.2 SB51.2 T2.1(S) T2.2(S) T2.5(D) T2.6(D)
DSI.CK_N: CN2.3 ; port DSI.CK_N
DSI.CK_P: CN2.5 ; port DSI.CK_P
DSI.D0_N: CN2.11 ; port DSI.D0_N
DSI.D0_P: CN2.9 ; port DSI.D0_P
DSI.D1_N: CN2.17 ; port DSI.D1_N
DSI.D1_P: CN2.15 ; port DSI.D1_P
DSI_BL_CTRL: CN2.53 ; port DSI_BL_CTRL
DSI_PWR_ON: R73.1 R74.1 R75.1 R76.1 R78.1 ; port DSI_PWR_ON
DSI_RESETn: CN2.57 R71.2 ; port DSI_RESETn
DSI_SPI_CLK: SB17.2 ; port DSI_SPI.DSI_SPI_CK
DSI_SPI_D/CX: SB18.2 ; port DSI_SPI.DSI_SPI_DCX
DSI_SPI_MOSI: SB19.2 ; port DSI_SPI.DSI_SPI_MOSI
DSI_SPI_USART_CS: SB15.2 ; port DSI_SPI.DSI_SPI_CS
DSI_SWIRE: CN2.43 ; port DSI_SWIRE
DSI_TE: CN2.49 ; port DSI_TE
DSI_TOUCH_INT: CN2.4 R72.1 ; port DSI_TOUCH_INT
I2C5.SCL: CN2.44 R70.2 ; port I2C5.SCL
I2C5.SDA: CN2.40 R69.2 ; port I2C5.SDA
SPI_CLK: CN2.24 SB16.1 SB17.1
SPI_D/CX: CN2.28 SB18.1
SPI_MOSI: CN2.26 SB14.1 SB19.1
SPI_USART_CS: CN2.22 SB15.1
USART3_CK: SB16.2 ; port DSI_USART.DSI_USART_CK  [project net PD10]
USART3_TX: SB14.2 ; port DSI_USART.DSI_USART_TX  [project net PB10]
NetC119_1: C119.1 C120.2 CN2.21 CN2.23 L4.2
NetC121_1: C121.1 R73.2 T1.3(G)
NetC122_1: C122.1 R74.2 T4.3(G)
NetC123_1: C123.1 R75.2 T3.3(G)
NetC124_1: C124.1 R76.2 T2.3(G)
NetCN2_8: CN2.8 R17.1
NetCN2_10: CN2.10 R18.1
NetCN2_14: CN2.14 R16.1
NetCN2_16: CN2.16 R19.1
NetR69_1: R69.1 R70.1 SB50.1

Not connected (* = marked no-connect by the designer): CN2 2* 20* 25* 30* 31* 32* 33* 34* 35* 37* 39* 41* 42* 45* 46* 47* 48* 50* 51* 52* 54* 55* 56* 58* 59*

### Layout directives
differential pair; rule Impedance Constraint [Min = 95.00    Max = 105.0    ]; rule Matched Net Lengths [Tolerance = 5mil]: DSI.CK_N
differential pair; rule Impedance Constraint [Min = 95.00    Max = 105.0    ]; rule Matched Net Lengths [Tolerance = 0mil]: DSI.CK_P, DSI.D0_N, DSI.D0_P, DSI.D1_N, DSI.D1_P

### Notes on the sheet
- DSI LCD
- DSI.CK_N and DSI.CK_P are inverted on DSI connector pins : swap lanes in Software
- PB10
- DSI_D2_P
- PE8
- PD10
- DSI_D2_N
- DSI_D3_P
- DSI_D3_N
- (near SB17) PD11
- (near SB17) PD4
- (near SB17) PD8
- (near SB17) PB13
- PI7
- PI6
- PF11
- (near R71) PD5
- PH5
- PH4
- Adapt resistors if needed
- (near R78) PI5

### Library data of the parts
C22-C24 C120 = MCD-00006: as C71 on sheet USBHS_TYPEC
C119 = MCD-00199: Capacitor, Tantalum, 10uF, 16V, 3R, +/-10%, Type_A (3216 metric), T=1.6mm; Manufacturer_Part_Number: TAJA106K016R; Manufacturer: AVX; BMS_Part_Number: 9141044; Part_Preference: Recommended; Order_Code_RS: 699-2848; Component_Country_Of_Origin: El Salvador
C121-C124 = MCD-01101: Capacitor, MLCC, 100pF, 50V, X7R, +/-5%, 0603, T=0.33mm; Manufacturer_Part_Number: 06035C101JAT4A; Manufacturer: AVX; Part_Preference: Recommended; Component_Country_Of_Origin: China
CN2 = MCD-02128: Socket, 30x2, 0.5mm, VR, SMD, T=3.05mm; Part_Type: Connector; Manufacturer: SAMTEC; Part_Preference: Recommended; Order_Code_RS: 180-2587; Component_Country_Of_Origin: China, Costa Rica, Malaysia, United States, Vietnam
L4 L5 = MCD-00047: Ferrite bead, 600R @1 00MHz, +/-25%, 350mA, 0R5, 0603, T=0.8mm; Part_Type: Inductor; Manufacturer_Part_Number: FCM1608KF-601T03; Manufacturer: TAI-TECH; Part_Preference: Recommended; Component_Country_Of_Origin: Unknown
R16-R19 = MCD-00052: as R41 on sheet USBHS_TYPEC
R69 R70 = MCD-00184: Resistor, 3K3, 0402, +/-1%, 1/16W; BMS_Part_Number: 9131946; Manufacturer: YAGEO; Manufacturer_Part_Number: RC0402FR-073K3L; Part_Preference: Recommended; Component_Country_Of_Origin: China
R71 R72 = MCD-00053: as R112-R114 on sheet eMMC
R73-R76 = MCD-00056: Resistor, 0R, 0603, +/-5%, 1/10W; Manufacturer_Part_Number: RC0603JR-070RL; Manufacturer: YAGEO; Part_Preference: Recommended; Component_Country_Of_Origin: China
R78 = MCD-00495: Resistor, 560K, 0402, +/-1%, 1/16W; Manufacturer_Part_Number: RC0402FR-07560KL; Manufacturer: YAGEO; Part_Preference: Recommended; Component_Country_Of_Origin: China; ShowFields: YES; ID: 2779
SB14-SB19 = MCD-02162: as SB39 on sheet eMMC
SB49-SB53 = MCD-01618: as SB41 on sheet eMMC
T1-T3 = MCD-01926: 20 V, P-channel Trench MOSFET; Part_Type: IC; Manufacturer_Part_Number: PMN30XPX; Manufacturer: NEXPERIA; Part_Preference: Recommended; Order_Code_RS: 153-0671; Component_Country_Of_Origin: China
T4 = MCD-03170: Transistor, MOSFET, P-CH, -20V, 7A, SOT457; Part_Preference: Recommended; Manufacturer: NEXPERIA; Partial_Alternate_Internal_Part_Number: MCD-01926; ShowFields: YES; ID: 5286; Component_Country_Of_Origin: China°

## Sheet MEMS.SchDoc: MEMS
size A4; Date: Not used; ApprovedBy: Not used; CheckedBy: Not used; Author: Not used; CompanyName: STMicroelectronics; DrawnBy: Not used; Engineer: Not used; Organization: Not used; Address1: Not used; Address2: Not used; Address3: Not used; Address4: Not used; DocumentNumber: Not used; Revision: Not used; SheetNumber: 12; SheetTotal: 16
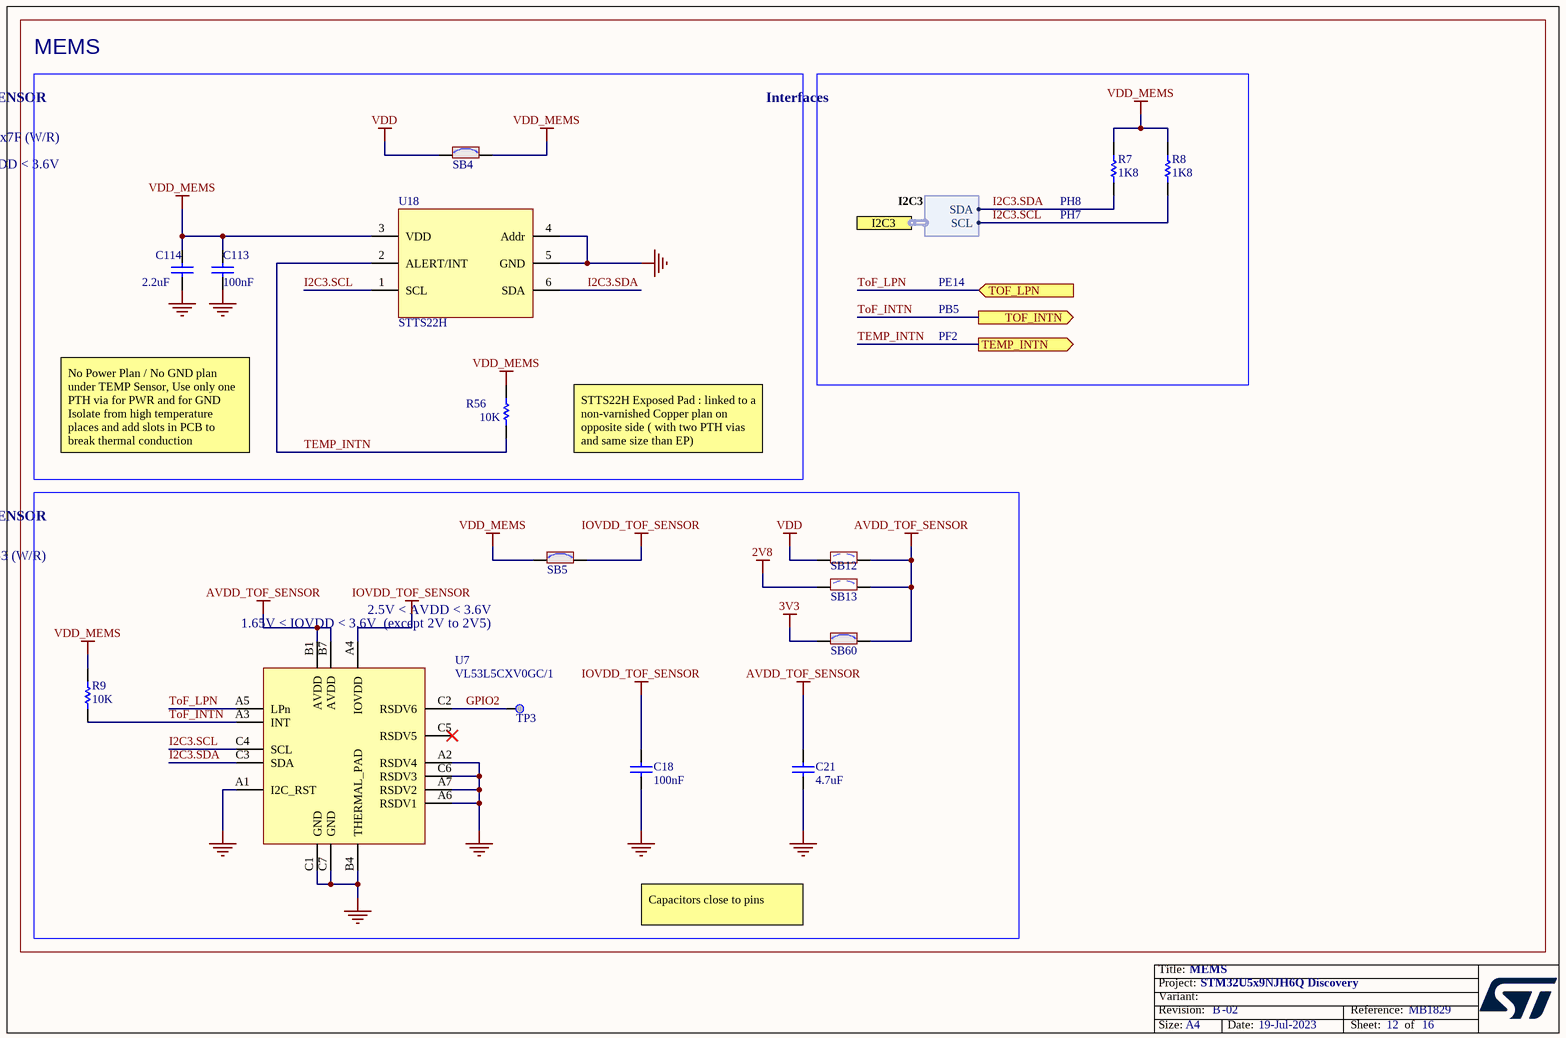
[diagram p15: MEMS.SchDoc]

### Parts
C18  value 100nF  [C0603]  (hidden comment: Capacitor)
C21  value 4.7uF  [C0603_H0P8]  (hidden comment: Capacitor)
C113  value 100nF  [C0603]  (hidden comment: Capacitor)
C114  value 2.2uF  [C0603]  (hidden comment: Capacitor)
R7  value 1K8  [R0402]  (hidden comment: Resistor)
R8  value 1K8  [R0402]  (hidden comment: Resistor)
R9  value 10K  [R0603]  (hidden comment: Resistor)
R56  value 10K  [R0603]  (hidden comment: Resistor)
SB4  SB_ON  [SOLDER-BRIDGE_R0402-0R]  (value not drawn)
SB5  SB_ON  [SOLDER-BRIDGE_R0402-0R]  (value not drawn)
SB12  SB_OFF  [SOLDER-BRIDGE_R0402-0R]  (value not drawn)
SB13  SB_OFF  [SOLDER-BRIDGE_R0402-0R]  (value not drawn)
SB60  SB_ON  [SOLDER-BRIDGE_R0402-0R]  (value not drawn)
TP3  Test Point  [TP_SMD_1MM]  (value not drawn)  (no BOM)
U7  VL53L5CXV0GC/1  [ICC_LGA16_6P4X3_P075_H1P5]
U18  STTS22H  [ICC_UDFN6-EPAD_2X2_P065]

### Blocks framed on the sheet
MEMS: C113 C114 R56 SB4 U18
Interfaces: R7 R8
TIME OF FLIGHT SENSOR: C18 C21 R9 SB5 SB12 SB13 SB60 TP3 U7

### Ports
I2C3 (harness I2C3), TEMP_INTN (out), TOF_INTN (out), TOF_LPN (in)

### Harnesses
I2C3: SDA, SCL

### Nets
2V8: SB13.1
3V3: SB60.1
AVDD_TOF_SENSOR: C21.2 SB12.2 SB13.2 SB60.2 U7.B1(AVDD) U7.B7(AVDD)
GND: C18.2 C21.1 C113.2 C114.1 U7.A1(I2C_RST) U7.A2(RSDV4) U7.A6(RSDV1) U7.A7(RSDV2) U7.B4(THERMAL_PAD) U7.C1(GND) U7.C6(RSDV3) U7.C7(GND) U18.4(Addr) U18.5(GND)
IOVDD_TOF_SENSOR: C18.1 SB5.2 U7.A4(IOVDD)
VDD: SB4.1 SB12.1
VDD_MEMS: C113.1 C114.2 R7.2 R8.2 R9.2 R56.2 SB4.2 SB5.1 U18.3(VDD)
GPIO2: TP3.1 U7.C2(RSDV6)
I2C3.SCL: R8.1 U7.C4(SCL) U18.1(SCL) ; port I2C3.SCL
I2C3.SDA: R7.1 U7.C3(SDA) U18.6(SDA) ; port I2C3.SDA
TEMP_INTN: R56.1 U18.2(ALERT/INT) ; port TEMP_INTN
ToF_INTN: R9.1 U7.A3(INT) ; port TOF_INTN
ToF_LPN: U7.A5(LPn) ; port TOF_LPN

Not connected (* = marked no-connect by the designer): U7 C5(RSDV5)*

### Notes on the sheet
- TEMPERATURE SENSOR
- 1.5V < VDD < 3.6V
- I2C Default address : 0x7E / 0x7F (W/R)
- (near R7) PH7
- (near R7) PH8
- PE14
- PB5
- PF2
- No Power Plan / No GND plan under TEMP Sensor, Use only one PTH via for PWR and for GND
  Isolate from high temperature places and add slots in PCB to break thermal conduction
- STTS22H Exposed Pad : linked to a non-varnished Copper plan on opposite side ( with two PTH vias and same size than EP)
- I2C Default address : 0x52 / 0x53 (W/R)
- 1.65V < IOVDD < 3.6V  (except 2V to 2V5)
- (near SB5) 2.5V < AVDD < 3.6V
- Capacitors close to pins

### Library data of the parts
C18 C113 = MCD-00211: Capacitor, MLCC, 100nF, 16V, X7R, +/-10%, 0603, T=0.8mm; Manufacturer_Part_Number: CC0603KRX7R7BB104; Manufacturer: YAGEO; Part_Preference: Recommended; Order_Code_RS: 669-8763
C21 = MCD-01721: Capacitor, MLCC, 4.7uF, 10V, X5R, +/-10%, 0603, T=0.8mm; Part_Preference: Recommended; Manufacturer: YAGEO; Manufacturer_Part_Number: CC0603KRX5R6BB475
C114 = MCD-00012: Capacitor, MLCC, 2.2uF, 10V, X5R, +/- 10%, 0603, T=0.8mm; BMS_Part_Number: 9142010; Part_Preference: Recommended; Manufacturer: YAGEO; Manufacturer_Part_Number: CC0603KRX5R6BB225; Alternate_Manufacturer: KEMET; Alternate_Manufacturer_Part_Number: C0603C225K8PACTU
R7 R8 = MCD-00409: Resistor, 1K8, 0402, +/-1%, 1/16W; Manufacturer_Part_Number: RC0402FR-071K8L; Manufacturer: YAGEO; Part_Preference: Recommended; Component_Country_Of_Origin: China
R9 R56 = MCD-00220: Resistor, 10K, 0603, +/-1%, 1/10W; Manufacturer_Part_Number: RC0603FR-0710KL; Manufacturer: YAGEO; Part_Preference: Recommended
SB4 SB5 SB60 = MCD-01618: as SB41 on sheet eMMC
SB12 = MCD-02162: as SB39 on sheet eMMC
SB13 = MCD-02162: Solder Bridge 0402 OFF; Part_Type: Misc; Manufacturer_Part_Number: RC0402JR-070RL; Manufacturer: YAGEO; Part_Preference: Recommended; Order_Code_RS: 618-5804; Component_Country_Of_Origin: China; ShowFields: YES; ID: 4262
TP3 = MCD-00074: Test Point 1mm; Part_Type: Misc; Part_Preference: Recommended
U7 = MCD-02590: Time-of-Flight 8x8 multizone ranging sensor with wide field of view; Part_Type: IC; Part_Preference: Recommended; Manufacturer: STMICROELECTRONICS; ShowFields: YES; ID: 4696
U18 = MCD-02159: temperature sensor; Part_Type: IC; Part_Preference: Recommended; Manufacturer: STMICROELECTRONICS; Manufacturer_HQ_COO: EU; Order_code_RS: 194-7646; Component_Country_Of_Origin: Thailand

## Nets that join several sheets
1V8: EXPANSION_CONNECTORS (CN9.15), AUDIO (SB2.1), BOARD_POWER (C117.2 R59.2 R62.2 TP2.1), DSI_LCD (SB49.1 T1.4)
2V8: BOARD_POWER (C118.2 R66.2 TP1.1), MEMS (SB13.1)
3V3: EXPANSION_CONNECTORS (CN9.7), AUDIO (C1.2 U4.1), BOARD_POWER (JP1.2 R57.1 R77.2), MCU_CLOCK_AND_USER_INTERFACE (R116.2 R125.2), MCU_PWR (SB37.1), USBHS_TYPEC (C71.2 R120.2 U9.1 U11.12), eMMC (SB41.1), DSI_LCD (SB53.1 T3.4), MEMS (SB60.1)
5V: EXPANSION_CONNECTORS (SB54.1), BOARD_POWER (11 pins), ST_LINK_V3E (R54.1), DSI_LCD (R78.2 SB52.1 T4.4)
5V_STLK: BOARD_POWER (JP4.1), ST_LINK_V3E (C141.2 U29.1)
5V_UCPD: BOARD_POWER (JP4.5), ST_LINK_V3E (D1.1), USBHS_TYPEC (7 pins)
5V_USB_CHGR: BOARD_POWER (JP4.7), ST_LINK_V3E (8 pins)
5V_VIN: EXPANSION_CONNECTORS (SB26.1), BOARD_POWER (JP4.3), ST_LINK_V3E (D3.1)
AGND: EXPANSION_CONNECTORS (C25.1 C125.1 CN10.25), MCU_PWR (9 pins)
GND: EXPANSION_CONNECTORS (5 pins), AUDIO (20 pins), BOARD_POWER (36 pins), MCU_CLOCK_AND_USER_INTERFACE (18 pins), MCU_PWR (52 pins), MECHANICAL (7 pins), OCTOSPI_FLASH (9 pins), ST_LINK_V3E (109 pins), USBHS_TYPEC (32 pins), eMMC (32 pins), HEXADECASPI_PSRAM (6 pins), DSI_LCD (20 pins), MEMS (14 pins)
VDD: EXPANSION_CONNECTORS (SB56.1), AUDIO (6 pins), BOARD_POWER (JP2.2 R62.1 R79.1), MCU_CLOCK_AND_USER_INTERFACE (B1.3 B1.4 SW1.2), OCTOSPI_FLASH (SB27.1), ST_LINK_V3E (8 pins), USBHS_TYPEC (C72.1 R36.2 U9.8), eMMC (SB39.1 SB44.1), HEXADECASPI_PSRAM (SB47.1), DSI_LCD (SB51.1 T2.4), MEMS (SB4.1 SB12.1)
VDD_MCU: BOARD_POWER (JP3.2), MCU_PWR (31 pins)
VDDA: EXPANSION_CONNECTORS (C25.2 CN10.23), MCU_PWR (5 pins)
VREFP: EXPANSION_CONNECTORS (C125.2 SB55.2), MCU_PWR (C41.2 C43.2 SB31.1 U25.L5)
AUDIO_MEMs_LED: AUDIO (R1.2 R2.1 U4.7), MCU_IO (U25.M9)
Audio_RSTn: AUDIO (R5.2 U5.25), MCU_IO (U25.D11)
DSI.CK_N: MCU_IO (U25.J1), DSI_LCD (CN2.3)
DSI.CK_P: MCU_IO (U25.H1), DSI_LCD (CN2.5)
DSI.D0_N: MCU_IO (U25.G2), DSI_LCD (CN2.11)
DSI.D0_P: MCU_IO (U25.G1), DSI_LCD (CN2.9)
DSI.D1_N: MCU_IO (U25.K1), DSI_LCD (CN2.17)
DSI.D1_P: MCU_IO (U25.K2), DSI_LCD (CN2.15)
DSI_BL_CTRL: MCU_IO (U25.D5), DSI_LCD (CN2.53)
DSI_PWR_ON: MCU_IO (U25.C4), DSI_LCD (5 pins)
DSI_RESETn: MCU_IO (U25.B8), DSI_LCD (CN2.57 R71.2)
DSI_SPI_CLK: EXPANSION_CONNECTORS (SB23.1), MCU_IO (U25.M12), DSI_LCD (SB17.2)
DSI_SPI_D/CX: EXPANSION_CONNECTORS (SB25.1), MCU_IO (U25.L12), DSI_LCD (SB18.2)
DSI_SPI_MOSI: EXPANSION_CONNECTORS (SB24.1), MCU_IO (U25.A8), DSI_LCD (SB19.2)
DSI_SPI_USART_CS: MCU_IO (U25.N13), DSI_LCD (SB15.2)
DSI_SWIRE: MCU_IO (U25.D4), DSI_LCD (CN2.43)
DSI_TE: MCU_IO (U25.P7), DSI_LCD (CN2.49)
DSI_TOUCH_INT: MCU_IO (U25.M8), DSI_LCD (CN2.4 R72.1)
eMMC_RSTn: MCU_IO (U25.C11), eMMC (R111.1)
HEXASPI1.CLK: MCU_IO (U25.J14), HEXADECASPI_PSRAM (U34.B2)
HEXASPI1.DQS0: MCU_IO (U25.J13), HEXADECASPI_PSRAM (U34.C3)
HEXASPI1.DQS1: MCU_IO (U25.H13), HEXADECASPI_PSRAM (U34.B3)
HEXASPI1.IO0: MCU_IO (U25.L13), HEXADECASPI_PSRAM (U34.D3)
HEXASPI1.IO1: MCU_IO (U25.L14), HEXADECASPI_PSRAM (U34.D2)
HEXASPI1.IO2: MCU_IO (U25.M15), HEXADECASPI_PSRAM (U34.C4)
HEXASPI1.IO3: MCU_IO (U25.L15), HEXADECASPI_PSRAM (U34.D4)
HEXASPI1.IO4: MCU_IO (U25.K13), HEXADECASPI_PSRAM (U34.D5)
HEXASPI1.IO5: MCU_IO (U25.K14), HEXADECASPI_PSRAM (U34.E3)
HEXASPI1.IO6: MCU_IO (U25.K15), HEXADECASPI_PSRAM (U34.E2)
HEXASPI1.IO7: MCU_IO (U25.J12), HEXADECASPI_PSRAM (U34.E1)
HEXASPI1.IO8: MCU_IO (U25.H12), HEXADECASPI_PSRAM (U34.C2)
HEXASPI1.IO9: MCU_IO (U25.G15), HEXADECASPI_PSRAM (U34.B1)
HEXASPI1.IO10: MCU_IO (U25.G14), HEXADECASPI_PSRAM (U34.A2)
HEXASPI1.IO11: MCU_IO (U25.G13), HEXADECASPI_PSRAM (U34.A4)
HEXASPI1.IO12: MCU_IO (U25.F15), HEXADECASPI_PSRAM (U34.A5)
HEXASPI1.IO13: MCU_IO (U25.F14), HEXADECASPI_PSRAM (U34.B4)
HEXASPI1.IO14: MCU_IO (U25.F13), HEXADECASPI_PSRAM (U34.B5)
HEXASPI1.IO15: MCU_IO (U25.E15), HEXADECASPI_PSRAM (U34.C5)
HEXASPI1.NCS: MCU_IO (U25.M14), HEXADECASPI_PSRAM (R52.1 U34.A3)
I2C1.SCL: EXPANSION_CONNECTORS (CN10.2 R29.1 SB7.1), MCU_IO (U25.D7)
I2C1.SDA: EXPANSION_CONNECTORS (CN10.4 R28.1 SB8.1), MCU_IO (U25.B6)
I2C3.SCL: MCU_IO (U25.B11), MEMS (R8.1 U7.C4 U18.1)
I2C3.SDA: MCU_IO (U25.D10), MEMS (R7.1 U7.C3 U18.6)
I2C4.SCL: AUDIO (R14.1 U5.3), MCU_IO (U25.A4)
I2C4.SDA: AUDIO (R13.1 U5.2), MCU_IO (U25.A3)
I2C5.SCL: MCU_IO (U25.B12), DSI_LCD (CN2.44 R70.2)
I2C5.SDA: MCU_IO (U25.C12), DSI_LCD (CN2.40 R69.2)
LED_GREEN: MCU_CLOCK_AND_USER_INTERFACE (R107.1), MCU_IO (U25.A2)
LED_RED: MCU_CLOCK_AND_USER_INTERFACE (R105.1), MCU_IO (U25.B3)
MIC.CCK0: AUDIO (CN1.4 U2.1), MCU_IO (U25.K4)
MIC.SDIN0: AUDIO (CN1.6 U1.1), MCU_IO (U25.K3)
MIC.SDIN4: AUDIO (CN1.5 U3.1), MCU_IO (U25.P10)
NRST: EXPANSION_CONNECTORS (CN9.5), MCU_CLOCK_AND_USER_INTERFACE (B2.1 B2.2 C28.2 U8.1), MCU_IO (U25.R2), OCTOSPI_FLASH (R20.1 R22.1), ST_LINK_V3E (CN3.10 CN11.12 R117.1 U30.5)
OCTOSPIM_P1.CLK: MCU_IO (U25.L1), OCTOSPI_FLASH (U22.B2)
OCTOSPIM_P1.DQS: MCU_IO (U25.P3), OCTOSPI_FLASH (U22.C3)
OCTOSPIM_P1.IO0: MCU_IO (U25.M3), OCTOSPI_FLASH (U22.D3)
OCTOSPIM_P1.IO1: MCU_IO (U25.L4), OCTOSPI_FLASH (U22.D2)
OCTOSPIM_P1.IO2: MCU_IO (U25.L3), OCTOSPI_FLASH (U22.C4)
OCTOSPIM_P1.IO3: MCU_IO (U25.M2), OCTOSPI_FLASH (U22.D4)
OCTOSPIM_P1.IO4: MCU_IO (U25.M1), OCTOSPI_FLASH (U22.D5)
OCTOSPIM_P1.IO5: MCU_IO (U25.P1), OCTOSPI_FLASH (U22.E3)
OCTOSPIM_P1.IO6: MCU_IO (U25.N3), OCTOSPI_FLASH (U22.E2)
OCTOSPIM_P1.IO7: MCU_IO (U25.P2), OCTOSPI_FLASH (U22.E1)
OCTOSPIM_P1.NCS: MCU_IO (U25.M4), OCTOSPI_FLASH (R23.2 R24.1 R25.1)
PA0: EXPANSION_CONNECTORS (CN9.21), MCU_IO (U25.N4)
PA3: EXPANSION_CONNECTORS (CN10.32), MCU_IO (U25.P4)
PA4: EXPANSION_CONNECTORS (CN9.25), MCU_IO (U25.M5)
PA5: EXPANSION_CONNECTORS (SB9.1), MCU_IO (U25.R4)
PA6: EXPANSION_CONNECTORS (CN9.30), MCU_IO (U25.P5)
PA7: EXPANSION_CONNECTORS (CN10.18), MCU_IO (U25.R5)
PB0: EXPANSION_CONNECTORS (CN9.22), MCU_IO (U25.N6)
PB1: EXPANSION_CONNECTORS (CN9.28), MCU_IO (U25.M6)
PB2: EXPANSION_CONNECTORS (CN9.19), MCU_IO (U25.R7)
PB3: EXPANSION_CONNECTORS (SB33.2), MCU_IO (SB34.2 U25.E7)
PB4: EXPANSION_CONNECTORS (CN9.8), MCU_IO (U25.D6)
PB10: EXPANSION_CONNECTORS (SB48.2), MCU_IO (U25.N12), DSI_LCD (SB14.2)
PB11: EXPANSION_CONNECTORS (CN9.24), MCU_IO (U25.M10)
PB12: EXPANSION_CONNECTORS (SB21.1), MCU_IO (U25.M11)
PB14: EXPANSION_CONNECTORS (CN9.2), MCU_IO (U25.P13)
PB15: EXPANSION_CONNECTORS (SB45.2), MCU_IO (SB46.2 U25.R14)
PC4: EXPANSION_CONNECTORS (SB6.1), MCU_IO (U25.R6)
PC5: EXPANSION_CONNECTORS (CN9.23), MCU_IO (U25.P6)
PC14-OSC32_IN: MCU_CLOCK_AND_USER_INTERFACE (C128.1 X3.2), MCU_IO (U25.B1)
PC15-OSC32_OUT: MCU_CLOCK_AND_USER_INTERFACE (C127.1 X3.1), MCU_IO (U25.C1)
PD0: EXPANSION_CONNECTORS (CN10.35), MCU_IO (U25.D9)
PD1: EXPANSION_CONNECTORS (CN10.37), MCU_IO (U25.C9)
PD3: EXPANSION_CONNECTORS (SB20.1), MCU_IO (U25.A9)
PD6: EXPANSION_CONNECTORS (CN9.10), MCU_IO (U25.C8)
PD7: EXPANSION_CONNECTORS (CN9.12), MCU_IO (U25.D8)
PD9: EXPANSION_CONNECTORS (CN10.11), MCU_IO (U25.P15)
PD10: EXPANSION_CONNECTORS (SB22.1), MCU_IO (U25.P14), DSI_LCD (SB16.2)
PD12: EXPANSION_CONNECTORS (CN10.9), MCU_IO (U25.M13)
PD15: EXPANSION_CONNECTORS (CN10.28), MCU_IO (U25.K12)
PE2: EXPANSION_CONNECTORS (CN10.1), AUDIO (U5.30), MCU_IO (U25.E5)
PE4: EXPANSION_CONNECTORS (CN10.7), AUDIO (U5.1), MCU_IO (U25.B2)
PE5: EXPANSION_CONNECTORS (CN10.5), AUDIO (U5.31), MCU_IO (U25.D3)
PE6: EXPANSION_CONNECTORS (CN10.3), AUDIO (U5.32), MCU_IO (U25.E4)
PE7: EXPANSION_CONNECTORS (CN10.30), MCU_IO (U25.N9)
PE11: EXPANSION_CONNECTORS (CN10.26), MCU_IO (U25.P11)
PF0: EXPANSION_CONNECTORS (CN9.14), MCU_IO (U25.H3)
PF1: EXPANSION_CONNECTORS (CN9.16), MCU_IO (U25.J4)
PF5: EXPANSION_CONNECTORS (CN10.34), MCU_IO (U25.L2)
PF12: EXPANSION_CONNECTORS (CN10.24), MCU_IO (U25.N7)
PF13: EXPANSION_CONNECTORS (CN10.20), MCU_IO (U25.M7)
PF14: EXPANSION_CONNECTORS (CN10.29), MCU_IO (U25.R8)
PF15: EXPANSION_CONNECTORS (SB11.1), MCU_IO (SB57.1 U25.P8)
PG0: EXPANSION_CONNECTORS (SB10.1), MCU_IO (SB58.2 U25.R9)
PG7: EXPANSION_CONNECTORS (CN10.36), MCU_IO (U25.D13)
PG8: EXPANSION_CONNECTORS (CN10.38), MCU_IO (U25.E13)
PG9: EXPANSION_CONNECTORS (CN10.10), MCU_IO (U25.A7)
PG10: EXPANSION_CONNECTORS (CN10.12), MCU_IO (U25.B7)
PG11: EXPANSION_CONNECTORS (CN10.14), MCU_IO (U25.C7)
PG15: EXPANSION_CONNECTORS (CN10.16), MCU_IO (U25.A5)
PH0-OSC_IN: MCU_CLOCK_AND_USER_INTERFACE (R26.1), MCU_IO (U25.N1), ST_LINK_V3E (SB28.2)
PH1-OSC_OUT: MCU_CLOCK_AND_USER_INTERFACE (R27.1), MCU_IO (U25.N2)
PH3-BOOT0: MCU_CLOCK_AND_USER_INTERFACE (R55.1), MCU_IO (U25.B4)
SAI1.SD_B: AUDIO (U5.29), MCU_IO (U25.C3)
SDMMC1.CK: MCU_IO (U25.C10), eMMC (R114.1 U26.M6 U27.M6)
SDMMC1.CMD: MCU_IO (U25.B9), eMMC (R113.1 U26.M5 U27.M5)
SDMMC1.D0: MCU_IO (U25.A14), eMMC (R97.1 U26.A3 U27.A3)
SDMMC1.D1: MCU_IO (U25.C14), eMMC (R99.1 U26.A4 U27.A4)
SDMMC1.D2: MCU_IO (U25.A10), eMMC (R100.1 U26.A5 U27.A5)
SDMMC1.D3: MCU_IO (U25.B10), eMMC (R95.1 U26.B2 U27.B2)
SDMMC1.D4: MCU_IO (U25.C6), eMMC (R96.1 U26.B3 U27.B3)
SDMMC1.D5: MCU_IO (U25.C5), eMMC (R98.1 U26.B4 U27.B4)
SDMMC1.D6: MCU_IO (U25.C15), eMMC (R101.1 U26.B5 U27.B5)
SDMMC1.D7: MCU_IO (U25.B15), eMMC (R102.1 U26.B6 U27.B6)
T.JTDI: MCU_IO (SB42.1), ST_LINK_V3E (CN3.8 CN11.10 U33.1)
T.SWCLK: MCU_IO (U25.A12), ST_LINK_V3E (CN3.4 CN11.6 R126.1 U33.4)
T.SWDIO: MCU_IO (U25.C13), ST_LINK_V3E (CN3.2 CN11.4 R124.1 U33.5)
T.SWO: MCU_IO (SB34.1), ST_LINK_V3E (CN3.6 CN11.8 R127.1 U33.3)
T.VCP_RX: MCU_IO (U25.D12), ST_LINK_V3E (CN11.13 R110.2 U30.1)
T.VCP_TX: MCU_IO (U25.E12), ST_LINK_V3E (CN11.14 R118.1 U30.3)
TEMP_INTN: MCU_IO (U25.J3), MEMS (R56.1 U18.2)
ToF_INTN: MCU_IO (U25.B5), MEMS (R9.1 U7.A3)
ToF_LPN: MCU_IO (U25.R10), MEMS (U7.A5)
UCPD.ADC1: MCU_IO (SB38.1 SB58.1), USBHS_TYPEC (R39.2 R43.1)
UCPD.ADC2: MCU_IO (SB40.1 SB57.2), USBHS_TYPEC (R38.2 R40.1)
UCPD.DBn: MCU_IO (U25.P9), USBHS_TYPEC (R37.1 R41.1 U9.7)
UCPD.FLT: MCU_IO (U25.N11), USBHS_TYPEC (R36.1 U11.11)
USBC.HS_N: MCU_IO (U25.B14), USBHS_TYPEC (U35.2)
USBC.HS_P: MCU_IO (U25.B13), USBHS_TYPEC (U35.1)
USER_Button: MCU_CLOCK_AND_USER_INTERFACE (C29.2 R68.1), MCU_IO (U25.F4)
VBUS_SENSE: MCU_IO (U25.N8), USBHS_TYPEC (C59.2 R31.1 R32.2)

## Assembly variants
U5A9NJQ: not fitted C1 C2 C3 C4 C5 C6 C7 C8 C9 C10 C11 C12 C13 C14 C15 C16 C17 C19 C20 C29 C37 C82 C115 C116 C117 C118 C121 C122 C123 C124 C138 CN1 CN3 CN6 CN12 HW2 HW4 L1 LD1 Q2 R1 R2 R3 R4 R5 R6 R10 R11 R12 R13 R14 R15 R20 R23 R28 R29 R41 R57 R58 R59 R60 R61 R63 R64 R65 R66 R67 R73 R74 R75 R76 R77 R78 R79 R80 R85 R114 R121 R122 R123 T1 T2 T3 T4 U1 U2 U3 U4 U5 U6 U19 U20 U27; alternate parts U25 -> MCD-03270
U5G9NJQ: not fitted C3 C4 C5 C6 C7 C8 C9 C10 C11 C12 C13 C14 C15 C16 C17 C19 C20 C29 C37 C82 C115 C116 C117 C118 C121 C122 C123 C124 C138 CN3 CN6 CN12 HW2 HW4 L1 LD1 Q2 R2 R4 R5 R6 R10 R11 R12 R13 R14 R15 R20 R23 R28 R29 R41 R57 R58 R59 R60 R61 R63 R64 R65 R66 R67 R73 R74 R75 R76 R77 R78 R79 R80 R85 R114 R121 R122 R123 T1 T2 T3 T4 U5 U6 U19 U20 U26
